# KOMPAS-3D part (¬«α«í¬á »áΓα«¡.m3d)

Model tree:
1. Эскиз:1
2. Операция выдавливания:1
     Расстояние 1 = 4.7; Расстояние 2 = 4.7
3. Эскиз:2
4. Операция выдавливания:2
     Расстояние 1 = 4.7; Расстояние 2 = 3
5. Смещенная плоскость:1
     Расстояние = 2
6. Смещенная плоскость:2
     Расстояние = 2
7. Эскиз:3
8. Операция выдавливания:3
     Расстояние 1 = 4.7; Расстояние 2 = 1
9. Эскиз:4
10. Операция выдавливания:4
     Расстояние 1 = 4.7; Расстояние 2 = 1
11. Скругление:3
     Радиус = 1
12. Скругление:4
     Радиус = 1
13. Скругление:5
     Радиус = 1
14. Скругление:6
     Радиус = 0.3
15. Скругление:7
     Радиус = 0.3
16. Скругление:8
     Радиус = 1
17. Эскиз:5
18. Вырезать элемент выдавливания:1
     Расстояние 1 = 10.0883
19. Эскиз:6
20. Вырезать элемент выдавливания:2
     Расстояние 1 = 15
21. Эскиз:7
22. Операция выдавливания:5
     Расстояние 1 = 4.7; Расстояние 2 = 0.1
23. Скругление:9
     Радиус = 1
24. Скругление:10
     Радиус = 0.1
25. Ломаная:1
26. Перпендикулярная плоскость:1
27. Эскиз:8
28. Кинематическая операция:1
     Толщина стенки 1 = 1; Толщина стенки 2 = 1
29. Эскиз:9
30. Операция выдавливания:6
     Расстояние 1 = 0.3; Расстояние 2 = 0.1

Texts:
  Сплав АЛ8  ГОСТ 1583-93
